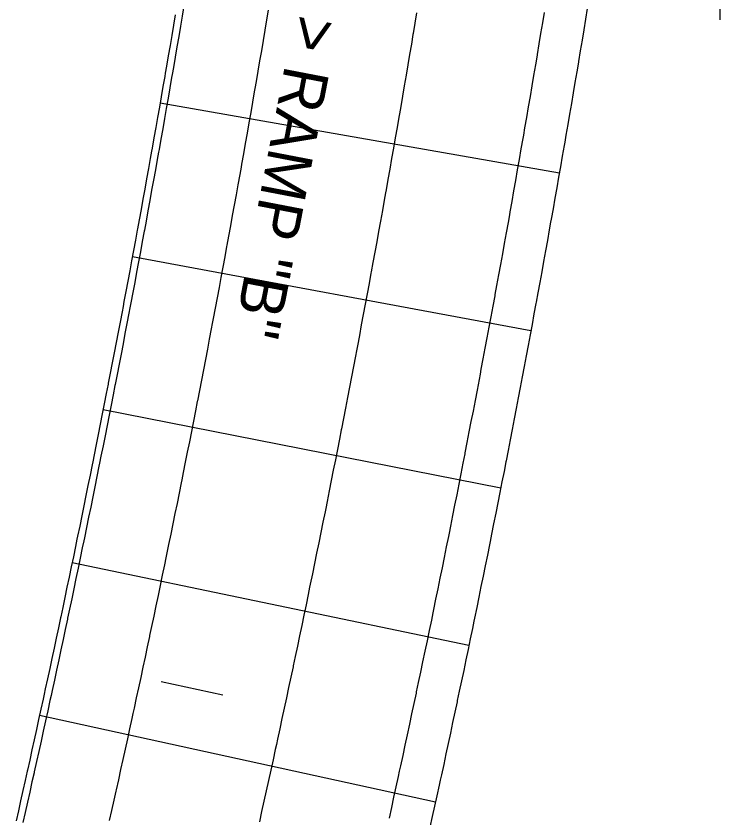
# Model space of a CAD drawing. Extents: x 2145147 to 2158018, y 137519 to 148068.
# Drawn here: x 2150674.7 to 2150741.8, y 144416.5 to 144493.1 of the extents above; entities that cross this region are included whole.
import ezdxf

# ---------------------------------------------------------------- set-up
doc = ezdxf.new("R2010")
doc.units = 0
for name, color, linetype in [('PR_Align_Ramp_B', 7, 'Continuous'), ('PR_Align_Ramp_B_Label', 7, 'Continuous'), ('PR_Align_Service_C_Leader', 7, 'Continuous'), ('PR_Joint_Contraction', 7, 'Continuous'), ('PR_Joint_Long', 7, 'Continuous'), ('PR_Road_Concrete', 7, 'Continuous')]:
    doc.layers.add(name, color=color, linetype=linetype)

msp = doc.modelspace()

# ---------------------------------------------------------------- linework, layer by layer
at = {"layer": 'PR_Align_Ramp_B'}
msp.add_lwpolyline([(2150694.38, 144428.26), (2150688.513, 144429.519)], dxfattribs=at)
at = {"layer": 'PR_Align_Service_C_Leader'}
msp.add_lwpolyline([(2150721.757, 144585.051), (2150741.818, 144526.722), (2150741.818, 144492.692)], dxfattribs=at)
at = {"layer": 'PR_Joint_Contraction'}
for p, q in [((2150726.495, 144478.068), (2150688.408, 144484.742)), ((2150723.777, 144463.018), (2150685.762, 144470.09)), ((2150720.901, 144447.998), (2150682.963, 144455.468)), ((2150717.868, 144433.009), (2150680.01, 144440.875)), ((2150714.678, 144418.052), (2150676.905, 144426.314))]:
    msp.add_line(p, q, dxfattribs=at)
at = {"layer": 'PR_Joint_Long'}
for points in [[(2150698.722, 144493.612), (2150698.57, 144492.705), (2150698.404, 144491.72), (2150698.237, 144490.735), (2150698.07, 144489.751), (2150697.901, 144488.767), (2150697.733, 144487.782), (2150697.563, 144486.798), (2150697.447, 144486.128), (2150697.393, 144485.815), (2150697.222, 144484.83), (2150697.05, 144483.847), (2150696.878, 144482.863), (2150696.705, 144481.88), (2150696.531, 144480.896), (2150696.357, 144479.913), (2150696.182, 144478.93), (2150696.132, 144478.651), (2150696.006, 144477.947), (2150695.83, 144476.964), (2150695.653, 144475.981), (2150695.475, 144474.998), (2150695.297, 144474.016), (2150695.118, 144473.033), (2150694.938, 144472.051), (2150694.778, 144471.18), (2150694.757, 144471.069), (2150694.576, 144470.087), (2150694.394, 144469.105), (2150694.212, 144468.123), (2150694.028, 144467.142), (2150693.844, 144466.16), (2150693.66, 144465.179), (2150693.474, 144464.197), (2150693.384, 144463.718), (2150693.289, 144463.217), (2150693.102, 144462.235), (2150692.914, 144461.255), (2150692.726, 144460.274), (2150692.538, 144459.293), (2150692.348, 144458.313), (2150692.158, 144457.332), (2150691.967, 144456.352), (2150691.95, 144456.263), (2150691.776, 144455.372), (2150691.584, 144454.392), (2150691.391, 144453.412), (2150691.197, 144452.433), (2150691.003, 144451.453), (2150690.808, 144450.474), (2150690.613, 144449.494), (2150690.477, 144448.815), (2150690.417, 144448.516), (2150690.22, 144447.536), (2150690.022, 144446.557), (2150689.824, 144445.579), (2150689.625, 144444.6), (2150689.425, 144443.622), (2150689.225, 144442.643), (2150689.024, 144441.665), (2150688.964, 144441.375), (2150688.822, 144440.687), (2150688.619, 144439.709), (2150688.416, 144438.732), (2150688.213, 144437.754), (2150688.008, 144436.777), (2150687.803, 144435.799), (2150687.597, 144434.822), (2150687.411, 144433.943), (2150687.391, 144433.845), (2150687.184, 144432.868), (2150686.976, 144431.892), (2150686.767, 144430.915), (2150686.558, 144429.939), (2150686.348, 144428.962), (2150686.137, 144427.986), (2150685.926, 144427.01), (2150685.82, 144426.52), (2150685.714, 144426.034), (2150685.502, 144425.059), (2150685.288, 144424.083), (2150685.074, 144423.108), (2150684.86, 144422.132), (2150684.644, 144421.157), (2150684.428, 144420.182), (2150684.211, 144419.207), (2150684.189, 144419.106), (2150683.994, 144418.233), (2150683.776, 144417.258), (2150683.557, 144416.284)], [(2150712.875, 144493.365), (2150712.709, 144492.37), (2150712.543, 144491.377), (2150712.529, 144491.295), (2150712.376, 144490.381), (2150712.208, 144489.387), (2150712.04, 144488.393), (2150711.87, 144487.398), (2150711.701, 144486.404), (2150711.53, 144485.411), (2150711.359, 144484.418), (2150711.242, 144483.74), (2150711.187, 144483.422), (2150711.015, 144482.43), (2150710.841, 144481.436), (2150710.667, 144480.443), (2150710.493, 144479.45), (2150710.317, 144478.457), (2150710.141, 144477.464), (2150709.965, 144476.473), (2150709.914, 144476.188), (2150709.787, 144475.478), (2150709.609, 144474.486), (2150709.43, 144473.494), (2150709.251, 144472.501), (2150709.07, 144471.509), (2150708.89, 144470.517), (2150708.708, 144469.526), (2150708.547, 144468.648), (2150708.525, 144468.532), (2150708.343, 144467.542), (2150708.159, 144466.55), (2150707.975, 144465.559), (2150707.79, 144464.568), (2150707.604, 144463.577), (2150707.418, 144462.586), (2150707.231, 144461.596), (2150707.139, 144461.11), (2150707.042, 144460.603), (2150706.854, 144459.614), (2150706.665, 144458.623), (2150706.475, 144457.633), (2150706.284, 144456.642), (2150706.093, 144455.652), (2150705.901, 144454.662), (2150705.709, 144453.675), (2150705.691, 144453.58), (2150705.515, 144452.683), (2150705.321, 144451.693), (2150705.126, 144450.704), (2150704.931, 144449.715), (2150704.735, 144448.726), (2150704.538, 144447.737), (2150704.341, 144446.748), (2150704.203, 144446.062), (2150704.142, 144445.758), (2150703.944, 144444.771), (2150703.744, 144443.782), (2150703.544, 144442.794), (2150703.343, 144441.806), (2150703.141, 144440.818), (2150702.939, 144439.83), (2150702.736, 144438.844), (2150702.675, 144438.548), (2150702.532, 144437.854), (2150702.328, 144436.867), (2150702.123, 144435.88), (2150701.917, 144434.893), (2150701.711, 144433.906), (2150701.503, 144432.919), (2150701.296, 144431.932), (2150701.108, 144431.046), (2150701.087, 144430.944), (2150700.878, 144429.959), (2150700.668, 144428.973), (2150700.457, 144427.986), (2150700.246, 144427), (2150700.034, 144426.015), (2150699.822, 144425.029), (2150699.608, 144424.044), (2150699.501, 144423.549), (2150699.394, 144423.057), (2150699.179, 144422.073), (2150698.964, 144421.088), (2150698.748, 144420.103), (2150698.531, 144419.118), (2150698.314, 144418.133), (2150698.096, 144417.149), (2150697.877, 144416.166)], [(2150725.044, 144493.404), (2150724.879, 144492.401), (2150724.712, 144491.398), (2150724.545, 144490.395), (2150724.378, 144489.392), (2150724.364, 144489.313), (2150724.209, 144488.389), (2150724.04, 144487.387), (2150723.87, 144486.384), (2150723.7, 144485.382), (2150723.529, 144484.38), (2150723.357, 144483.378), (2150723.184, 144482.376), (2150723.066, 144481.693), (2150723.011, 144481.374), (2150722.837, 144480.372), (2150722.662, 144479.37), (2150722.487, 144478.369), (2150722.311, 144477.367), (2150722.134, 144476.366), (2150721.956, 144475.365), (2150721.778, 144474.364), (2150721.727, 144474.08), (2150721.599, 144473.363), (2150721.42, 144472.362), (2150721.239, 144471.362), (2150721.058, 144470.361), (2150720.877, 144469.361), (2150720.694, 144468.361), (2150720.511, 144467.36), (2150720.348, 144466.474), (2150720.327, 144466.36), (2150720.143, 144465.36), (2150719.958, 144464.361), (2150719.772, 144463.361), (2150719.585, 144462.362), (2150719.398, 144461.362), (2150719.21, 144460.363), (2150719.021, 144459.364), (2150718.929, 144458.875), (2150718.832, 144458.365), (2150718.642, 144457.366), (2150718.451, 144456.367), (2150718.26, 144455.369), (2150718.067, 144454.37), (2150717.875, 144453.372), (2150717.681, 144452.374), (2150717.487, 144451.376), (2150717.469, 144451.284), (2150717.292, 144450.378), (2150717.096, 144449.38), (2150716.9, 144448.383), (2150716.703, 144447.385), (2150716.505, 144446.388), (2150716.307, 144445.391), (2150716.107, 144444.394), (2150715.969, 144443.701), (2150715.908, 144443.397), (2150715.707, 144442.4), (2150715.506, 144441.403), (2150715.304, 144440.407), (2150715.101, 144439.41), (2150714.898, 144438.414), (2150714.694, 144437.418), (2150714.489, 144436.422), (2150714.429, 144436.127), (2150714.284, 144435.426), (2150714.078, 144434.431), (2150713.871, 144433.435), (2150713.664, 144432.44), (2150713.456, 144431.445), (2150713.247, 144430.45), (2150713.037, 144429.455), (2150712.848, 144428.56), (2150712.827, 144428.46), (2150712.616, 144427.465), (2150712.404, 144426.471), (2150712.192, 144425.476), (2150711.979, 144424.482), (2150711.765, 144423.488), (2150711.551, 144422.494), (2150711.336, 144421.501), (2150711.227, 144421.002), (2150711.12, 144420.507), (2150710.903, 144419.513), (2150710.686, 144418.52), (2150710.468, 144417.527), (2150710.25, 144416.534)]]:
    msp.add_lwpolyline(points, dxfattribs=at)
at = {"layer": 'PR_Road_Concrete'}
for points in [[(2150690.681, 144494.033), (2150690.516, 144493.053), (2150690.35, 144492.074), (2150690.183, 144491.095), (2150690.016, 144490.117), (2150689.848, 144489.138), (2150689.68, 144488.159), (2150689.564, 144487.492), (2150689.51, 144487.181), (2150689.34, 144486.202), (2150689.17, 144485.224), (2150688.998, 144484.246), (2150688.826, 144483.268), (2150688.654, 144482.29), (2150688.48, 144481.312), (2150688.306, 144480.335), (2150688.257, 144480.057), (2150688.132, 144479.357), (2150687.956, 144478.38), (2150687.78, 144477.402), (2150687.603, 144476.425), (2150687.426, 144475.448), (2150687.248, 144474.471), (2150687.069, 144473.495), (2150686.91, 144472.629), (2150686.89, 144472.518), (2150686.709, 144471.541), (2150686.528, 144470.565), (2150686.347, 144469.589), (2150686.165, 144468.613), (2150685.982, 144467.636), (2150685.798, 144466.661), (2150685.614, 144465.685), (2150685.524, 144465.208), (2150685.429, 144464.709), (2150685.243, 144463.734), (2150685.057, 144462.758), (2150684.87, 144461.783), (2150684.682, 144460.808), (2150684.494, 144459.833), (2150684.305, 144458.858), (2150684.115, 144457.883), (2150684.098, 144457.794), (2150683.925, 144456.909), (2150683.734, 144455.934), (2150683.542, 144454.96), (2150683.35, 144453.986), (2150683.156, 144453.012), (2150682.963, 144452.038), (2150682.768, 144451.064), (2150682.633, 144450.388), (2150682.573, 144450.09), (2150682.377, 144449.117), (2150682.181, 144448.143), (2150681.984, 144447.17), (2150681.786, 144446.197), (2150681.587, 144445.224), (2150681.388, 144444.251), (2150681.188, 144443.279), (2150681.128, 144442.99), (2150680.987, 144442.306), (2150680.786, 144441.334), (2150680.584, 144440.361), (2150680.381, 144439.389), (2150680.178, 144438.417), (2150679.974, 144437.445), (2150679.77, 144436.474), (2150679.585, 144435.6), (2150679.564, 144435.502), (2150679.358, 144434.531), (2150679.151, 144433.559), (2150678.944, 144432.588), (2150678.736, 144431.617), (2150678.527, 144430.647), (2150678.318, 144429.676), (2150678.108, 144428.705), (2150678.002, 144428.218), (2150677.897, 144427.735), (2150677.686, 144426.765), (2150677.473, 144425.795), (2150677.261, 144424.825), (2150677.047, 144423.855), (2150676.833, 144422.885), (2150676.618, 144421.916), (2150676.403, 144420.946), (2150676.38, 144420.845), (2150676.187, 144419.977), (2150675.97, 144419.008), (2150675.752, 144418.039), (2150675.534, 144417.07), (2150675.315, 144416.102)], [(2150689.858, 144493.165), (2150689.693, 144492.186), (2150689.526, 144491.207), (2150689.359, 144490.229), (2150689.191, 144489.251), (2150689.023, 144488.273), (2150688.907, 144487.606), (2150688.853, 144487.295), (2150688.684, 144486.317), (2150688.513, 144485.339), (2150688.342, 144484.361), (2150688.17, 144483.384), (2150687.997, 144482.406), (2150687.824, 144481.429), (2150687.65, 144480.452), (2150687.601, 144480.174), (2150687.475, 144479.475), (2150687.3, 144478.498), (2150687.124, 144477.521), (2150686.947, 144476.544), (2150686.77, 144475.568), (2150686.592, 144474.591), (2150686.413, 144473.615), (2150686.254, 144472.749), (2150686.234, 144472.639), (2150686.054, 144471.663), (2150685.873, 144470.687), (2150685.692, 144469.711), (2150685.509, 144468.735), (2150685.327, 144467.76), (2150685.143, 144466.784), (2150684.959, 144465.809), (2150684.869, 144465.332), (2150684.774, 144464.834), (2150684.588, 144463.859), (2150684.402, 144462.884), (2150684.215, 144461.909), (2150684.028, 144460.934), (2150683.84, 144459.96), (2150683.651, 144458.985), (2150683.461, 144458.011), (2150683.444, 144457.922), (2150683.271, 144457.037), (2150683.08, 144456.063), (2150682.888, 144455.089), (2150682.696, 144454.115), (2150682.503, 144453.142), (2150682.309, 144452.168), (2150682.115, 144451.195), (2150681.979, 144450.519), (2150681.919, 144450.222), (2150681.724, 144449.248), (2150681.527, 144448.276), (2150681.33, 144447.303), (2150681.132, 144446.33), (2150680.934, 144445.358), (2150680.735, 144444.385), (2150680.535, 144443.413), (2150680.476, 144443.125), (2150680.334, 144442.441), (2150680.133, 144441.469), (2150679.931, 144440.497), (2150679.729, 144439.526), (2150679.526, 144438.554), (2150679.322, 144437.583), (2150679.117, 144436.611), (2150678.933, 144435.738), (2150678.912, 144435.64), (2150678.706, 144434.669), (2150678.499, 144433.698), (2150678.292, 144432.728), (2150678.084, 144431.757), (2150677.876, 144430.787), (2150677.666, 144429.817), (2150677.456, 144428.847), (2150677.351, 144428.36), (2150677.246, 144427.877), (2150677.034, 144426.907), (2150676.822, 144425.937), (2150676.61, 144424.968), (2150676.396, 144423.998), (2150676.182, 144423.029), (2150675.967, 144422.06), (2150675.752, 144421.091), (2150675.729, 144420.99), (2150675.536, 144420.122), (2150675.319, 144419.154), (2150675.102, 144418.185), (2150674.884, 144417.217), (2150674.665, 144416.249)], [(2150729.156, 144493.76), (2150728.991, 144492.754), (2150728.825, 144491.748), (2150728.658, 144490.742), (2150728.491, 144489.736), (2150728.323, 144488.731), (2150728.309, 144488.651), (2150728.154, 144487.725), (2150727.984, 144486.72), (2150727.814, 144485.715), (2150727.643, 144484.71), (2150727.471, 144483.705), (2150727.299, 144482.7), (2150727.126, 144481.695), (2150727.007, 144481.01), (2150726.952, 144480.691), (2150726.778, 144479.686), (2150726.602, 144478.682), (2150726.426, 144477.677), (2150726.25, 144476.673), (2150726.073, 144475.669), (2150725.895, 144474.665), (2150725.716, 144473.662), (2150725.665, 144473.376), (2150725.537, 144472.658), (2150725.356, 144471.654), (2150725.176, 144470.651), (2150724.994, 144469.648), (2150724.812, 144468.645), (2150724.629, 144467.642), (2150724.445, 144466.639), (2150724.282, 144465.75), (2150724.261, 144465.636), (2150724.076, 144464.633), (2150723.89, 144463.631), (2150723.704, 144462.628), (2150723.517, 144461.626), (2150723.329, 144460.624), (2150723.141, 144459.622), (2150722.951, 144458.62), (2150722.859, 144458.13), (2150722.762, 144457.619), (2150722.571, 144456.617), (2150722.38, 144455.616), (2150722.188, 144454.614), (2150721.995, 144453.613), (2150721.802, 144452.612), (2150721.608, 144451.611), (2150721.413, 144450.61), (2150721.395, 144450.519), (2150721.217, 144449.61), (2150721.021, 144448.609), (2150720.824, 144447.609), (2150720.627, 144446.609), (2150720.428, 144445.609), (2150720.229, 144444.609), (2150720.03, 144443.609), (2150719.891, 144442.915), (2150719.829, 144442.609), (2150719.628, 144441.61), (2150719.427, 144440.61), (2150719.224, 144439.611), (2150719.021, 144438.612), (2150718.817, 144437.613), (2150718.612, 144436.614), (2150718.407, 144435.615), (2150718.346, 144435.319), (2150718.201, 144434.617), (2150717.995, 144433.619), (2150717.787, 144432.62), (2150717.579, 144431.622), (2150717.371, 144430.624), (2150717.161, 144429.626), (2150716.951, 144428.629), (2150716.761, 144427.732), (2150716.74, 144427.631), (2150716.529, 144426.634), (2150716.316, 144425.637), (2150716.103, 144424.64), (2150715.89, 144423.643), (2150715.676, 144422.646), (2150715.461, 144421.649), (2150715.245, 144420.653), (2150715.136, 144420.153), (2150715.028, 144419.657), (2150714.811, 144418.66), (2150714.594, 144417.664), (2150714.375, 144416.669), (2150714.156, 144415.673)]]:
    msp.add_lwpolyline(points, dxfattribs=at)

# ---------------------------------------------------------------- texts
at = {"layer": 'PR_Align_Ramp_B_Label'}
msp.add_text('> RAMP "B"', height=4.3, rotation=259.12095, dxfattribs=at).set_placement((2150701.274, 144493.333))

doc.saveas('drawing.dxf')
